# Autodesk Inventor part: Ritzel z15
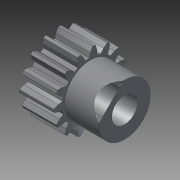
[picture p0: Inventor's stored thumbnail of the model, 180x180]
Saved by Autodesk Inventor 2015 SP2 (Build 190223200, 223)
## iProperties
Created: 2012-07
Part Number: Ritzel z15
Material: Stahl
Document SubType Name: Modeling
Designer: rYan
Mass: 1.81106 g
Surface Area: 4.00076 cm^2
Volume: 0.230709 cm^3
Density: 7.85 g/cm^3
Appearance: Platte
Übersetzungsnorm: STEP AP214IS
Dateiname: c:/PPEXPORT/antriebselemente_und_normteile/stirnzahnraeder/stirnzahnraeder_stahl/modul_05_und_07/artikel_nr___21101500.stp
Postprozessor: Build: 138, Release: 2013 RTM - Date: Thu 03/01/2012
Gesendete Einheiten: Millimeter
Unbestimmtheit: 1.0000000000000002e-06
Author: rYan
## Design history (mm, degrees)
node "11"
node "1"
node "Basis1"
